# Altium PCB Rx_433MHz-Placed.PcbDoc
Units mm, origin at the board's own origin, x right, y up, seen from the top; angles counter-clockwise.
Board outline 100 x 50 mm, 4 copper layers (SIGNAL_1, SIGNAL_2, SIGNAL_3, SIGNAL_4), stack 1.58 mm thick; 51 components, 60 nets, 198 pads, 0 vias.
Unrouted connection lines stored in the file: 118.
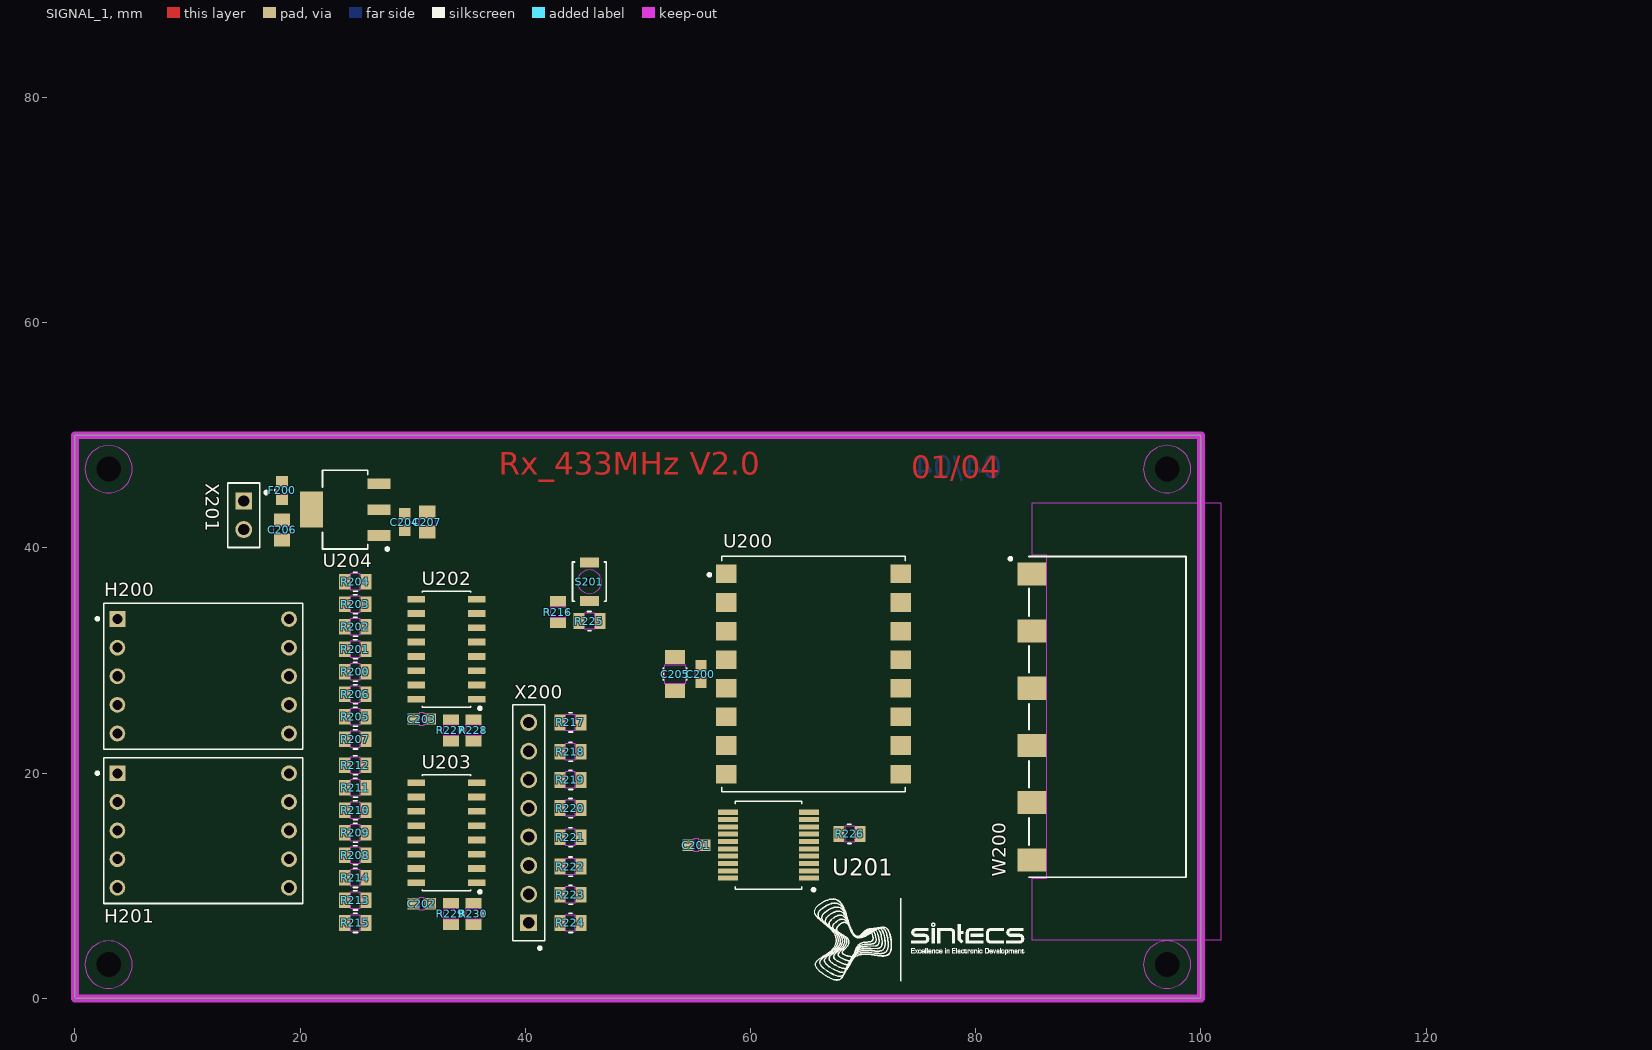
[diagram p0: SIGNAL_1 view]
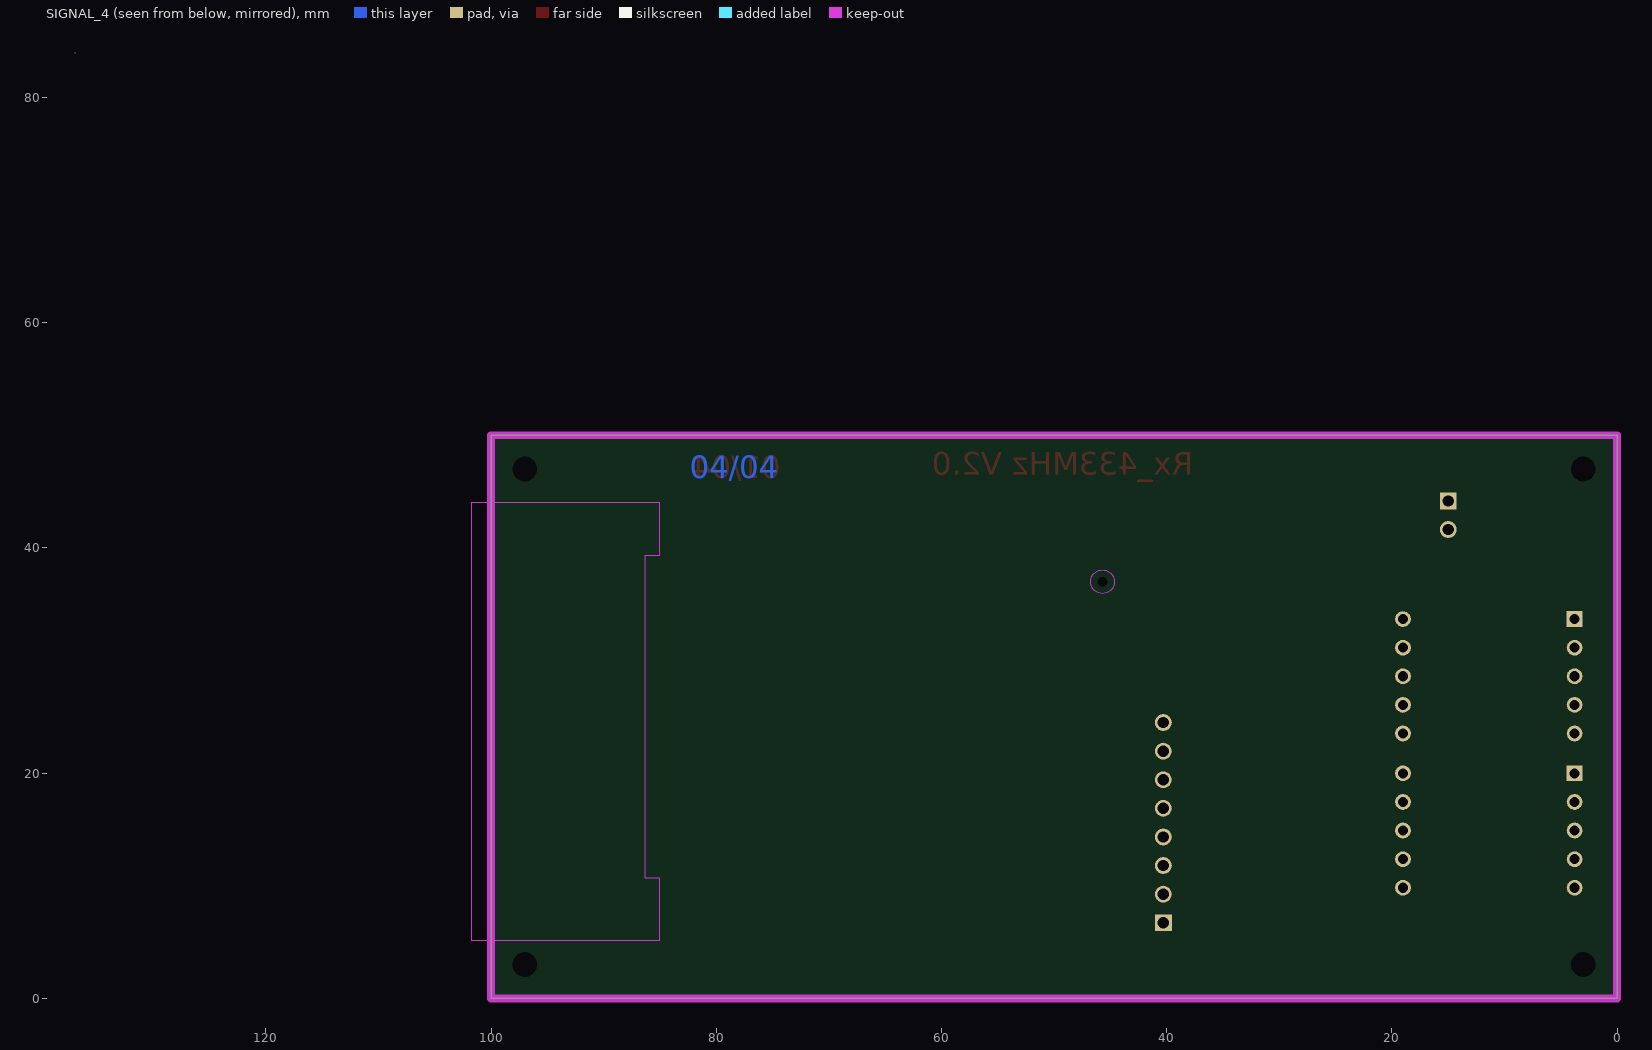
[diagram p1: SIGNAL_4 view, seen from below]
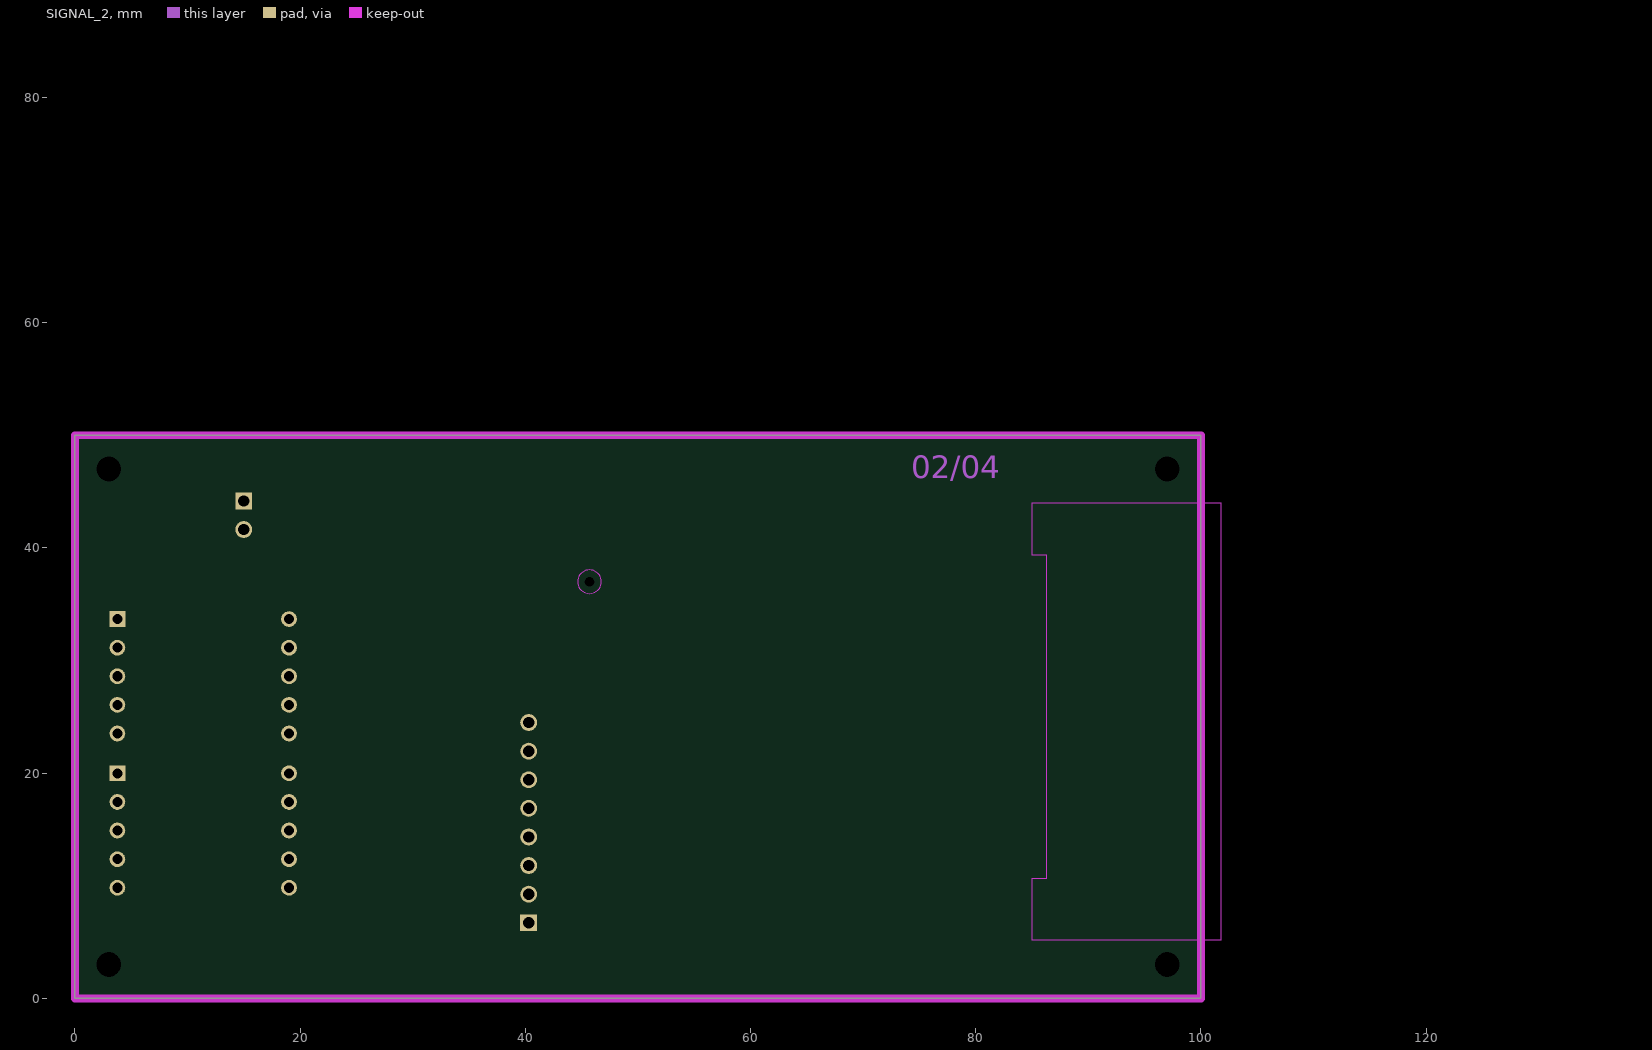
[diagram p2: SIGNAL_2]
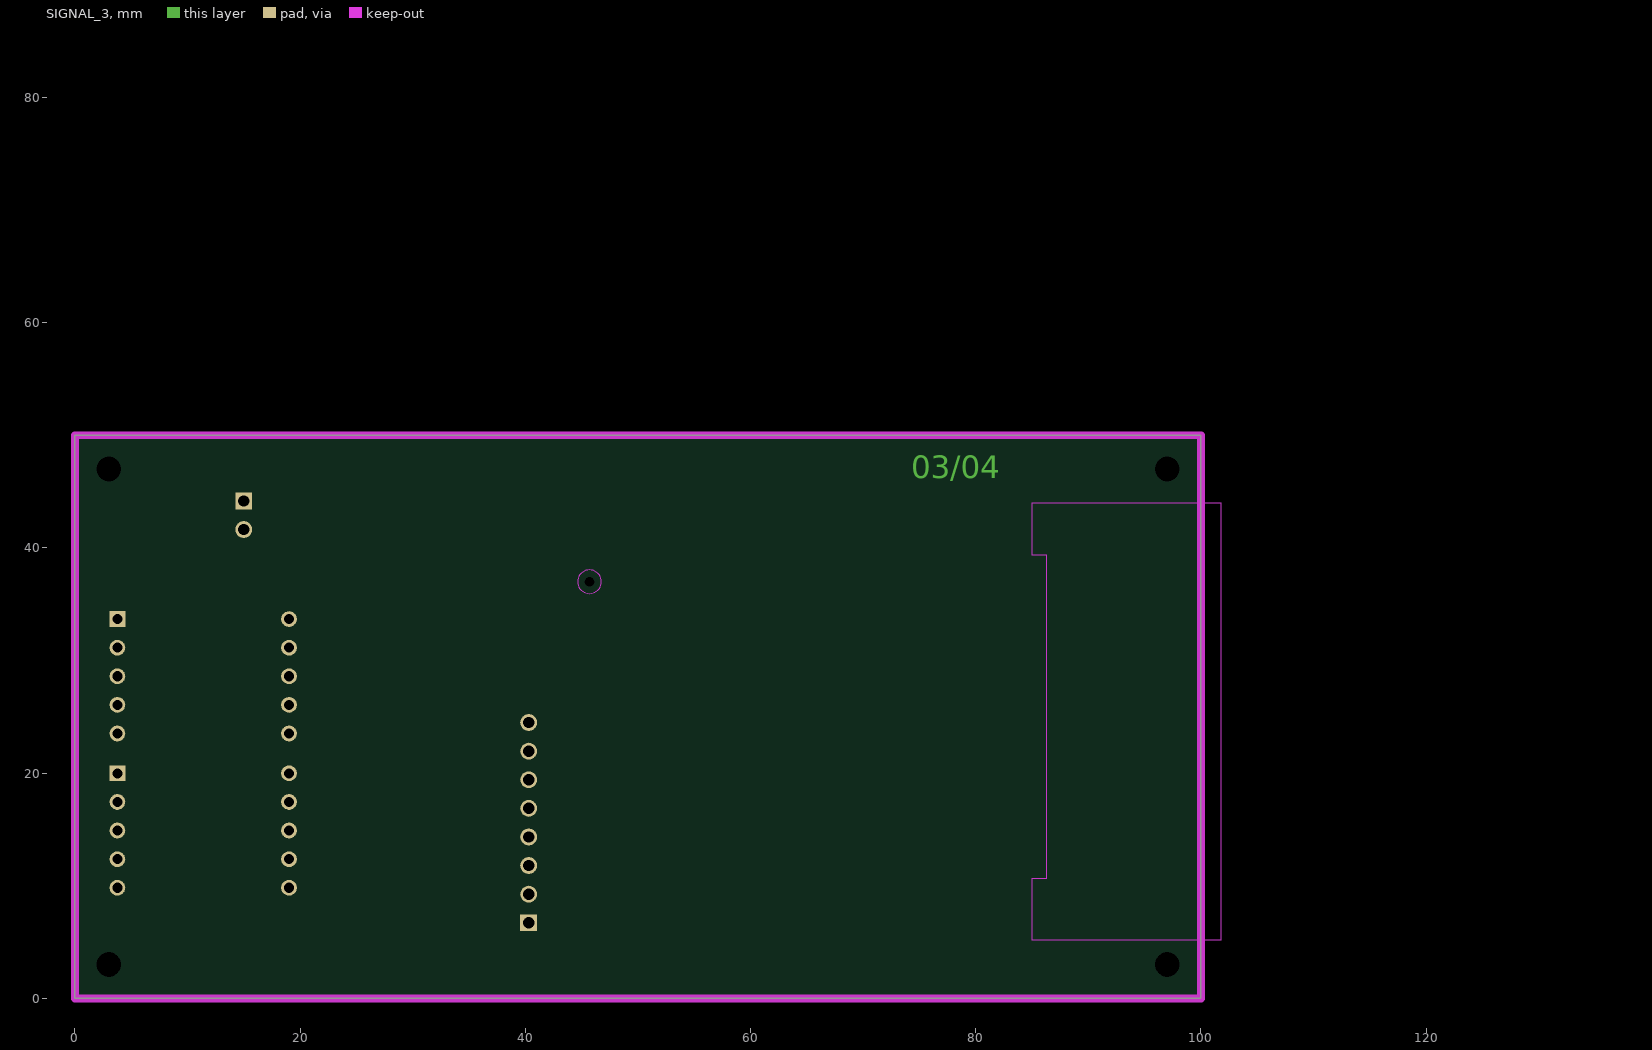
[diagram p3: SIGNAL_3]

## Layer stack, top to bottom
DIELECTRIC_1: solder mask 0.01, Dk 1
SIGNAL_1: signal copper 0.035
DIELECTRIC_3: prepreg 0.12, Dk 4.7
SIGNAL_2: signal copper 0.035
DIELECTRIC_5: prepreg 1.2, Dk 4.7
SIGNAL_3: signal copper 0.035
DIELECTRIC_7: prepreg 0.12, Dk 4.7
SIGNAL_4: signal copper 0.035
DIELECTRIC_9: solder mask 0.01, Dk 1

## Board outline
0,0 0,50 100,50 100,0

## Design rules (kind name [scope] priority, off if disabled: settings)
Clearance Clearance_50R [InNetClass('50R')] p1: gap=0.6 ignorepadtopadclearanceinfootprint=FALSE except(0.2: SMDPad-SMDPad)
Clearance [All] p2: gap=0.15 ignorepadtopadclearanceinfootprint=FALSE
ComponentClearance [All] p1: gap=0.1 collisioncheckmode=3 verticalgap=0.254 showdistances=FALSE
DiffPairsRouting [All] p1: maxlimit=0.254 minlimit=0.254 mostfreqgap=0.254 toplayer_minwidth=0.15 toplayer_maxwidth=0.3 toplayer_prefwidth=0.15 midlayer1_minwidth=0.15 midlayer1_maxwidth=0.3 midlayer1_prefwidth=0.15 midlayer2_minwidth=0.15 midlayer2_maxwidth=0.3 midlayer2_prefwidth=0.15 bottomlayer_minwidth=0.15 bottomlayer_maxwidth=0.3 bottomlayer_prefwidth=0.15 maxuncoupledlength=12.7
MinimumSolderMaskSliver [All] p1: minsoldermaskwidth=0.1
PolygonConnect [All] p1: thpad.connectstyle=Relief thpad.reliefconductorwidth=0.15 thpad.reliefentries=4 thpad.polygonreliefangle="90 Angle" thpad.airgapwidth=0.15 smdpad.connectstyle=Relief smdpad.reliefconductorwidth=0.15 smdpad.reliefentries=4 smdpad.polygonreliefangle="90 Angle" smdpad.airgapwidth=0.15 via.connectstyle=Direct via.reliefconductorwidth=0.127 via.reliefentries=2 via.polygonreliefangle="90 Angle" via.airgapwidth=0.152
RoutingVias [All] p1: holewidth=0.3 width=0.7 viastyle="Through Hole" minholewidth=0.3 minwidth=0.7 maxholewidth=0.3 maxwidth=0.7
SilkToSilkClearance [All] p1: silktosilkclearance=0.1
SolderMaskExpansion SolderMaskExpansion_Via [IsVia] p1: expansion=0.075 istentingtop=FALSE soldermaskfromhole=TRUE
SolderMaskExpansion [All] p2: expansion=0.1 istentingtop=FALSE
SupplyNets "Schematic Supply Nets_1" [InNet('3V3_RX')] p1: voltage=0.000
SupplyNets "Schematic Supply Nets" [InNet('GND_RX')] p2: voltage=0.000
UnRoutedNet [All] p1: checkbadconnections=TRUE
Width "Width for 50E_SE" [InNetClass('50R')] p1: maxlimit=0.2 minlimit=0.185 preferedwidth=0.2 toplayer_minwidth=0.2 bottomlayer_minwidth=0.2 impedanceprofiledriven=TRUE impedanceprofileid={877E34D1-77DC-4DEE-A0FB-207FE4FBDA97} impedanceprofilevalue=50.000000 minimp=50.000000 maximp=50.000000 favimp=50.000000
Width [All] p2: maxlimit=1 minlimit=0.15 preferedwidth=0.2
25 further rules are at their usual default settings.

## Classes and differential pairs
net class 50R: RF_RX
polygon class "\"(Inherited)\"": GND_RX_L02_P002

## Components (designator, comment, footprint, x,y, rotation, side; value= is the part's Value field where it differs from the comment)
C200 "C_0603_1608X90_GENERIC" CAPC1608X90N_0603_GENERIC 55.6,28.8 r90 top value=100nF
C201 "C_0603_1608X90_GENERIC" CAPC1608X90N_0603_GENERIC 55.2,13.6 r180 top value=100nF
C202 "C_0603_1608X90_GENERIC" CAPC1608X90N_0603_GENERIC 30.8,8.4 r0 top value=100nF
C203 "C_0603_1608X90_GENERIC" CAPC1608X90N_0603_GENERIC 30.8,24.8 r0 top value=100nF
C204 "C_0603_1608X90_GENERIC" CAPC1608X90N_0603_GENERIC 29.3,42.3 r270 top value=100nF
C205 "C_1206_3216X190_GENERIC" CAPC3216X190N_1206_GENERIC 53.3,28.8 r90 top value=10uF
C206 "08051C104KAZ2A" CAPC2013X140N_AVX 18.398,41.6 r270 top value=10uF
C207 "08051C104KAZ2A" CAPC2013X140N_AVX 31.3,42.3 r270 top value=10uF
F200 "0467XXXX" RESC1608X60N_0603_GENERIC 18.4,45.1 r90 top value=500mA
H200 "HDSP-5XXX" BROADCOM_HDSP-5XXX 11.4,28.6 r0 top
H201 "HDSP-5XXX" BROADCOM_HDSP-5XXX 11.4,14.9 r0 top
R200 "R_0805_2012X60_GENERIC" RESC2012X60N_0805_GENERIC 24.9,29.001 r180 top value=120R
R201 "R_0805_2012X60_GENERIC" RESC2012X60N_0805_GENERIC 24.9,31.001 r180 top value=120R
R202 "R_0805_2012X60_GENERIC" RESC2012X60N_0805_GENERIC 24.9,33.001 r180 top value=120R
R203 "R_0805_2012X60_GENERIC" RESC2012X60N_0805_GENERIC 24.9,35.001 r180 top value=120R
R204 "R_0805_2012X60_GENERIC" RESC2012X60N_0805_GENERIC 24.9,37.002 r180 top value=120R
R205 "R_0805_2012X60_GENERIC" RESC2012X60N_0805_GENERIC 24.9,25 r180 top value=120R
R206 "R_0805_2012X60_GENERIC" RESC2012X60N_0805_GENERIC 24.9,27 r180 top value=120R
R207 "R_0805_2012X60_GENERIC" RESC2012X60N_0805_GENERIC 24.9,23 r180 top value=120R
R208 "R_0805_2012X60_GENERIC" RESC2012X60N_0805_GENERIC 24.9,12.7 r180 top value=120R
R209 "R_0805_2012X60_GENERIC" RESC2012X60N_0805_GENERIC 24.9,14.7 r180 top value=120R
R210 "R_0805_2012X60_GENERIC" RESC2012X60N_0805_GENERIC 24.9,16.701 r180 top value=120R
R211 "R_0805_2012X60_GENERIC" RESC2012X60N_0805_GENERIC 24.9,18.701 r180 top value=120R
R212 "R_0805_2012X60_GENERIC" RESC2012X60N_0805_GENERIC 24.9,20.701 r180 top value=120R
R213 "R_0805_2012X60_GENERIC" RESC2012X60N_0805_GENERIC 24.9,8.7 r180 top value=120R
R214 "R_0805_2012X60_GENERIC" RESC2012X60N_0805_GENERIC 24.9,10.7 r180 top value=120R
R215 "R_0805_2012X60_GENERIC" RESC2012X60N_0805_GENERIC 24.9,6.7 r180 top value=120R
R216 "R_0805_2012X60_GENERIC" RESC2012X60N_0805_GENERIC 42.9,34.3 r270 top value=100K
R217 "R_0805_2012X60_GENERIC" RESC2012X60N_0805_GENERIC 44,24.5 r180 top value=1K
R218 "R_0805_2012X60_GENERIC" RESC2012X60N_0805_GENERIC 44,21.9 r180 top value=1K
R219 "R_0805_2012X60_GENERIC" RESC2012X60N_0805_GENERIC 44,19.4 r180 top value=1K
R220 "R_0805_2012X60_GENERIC" RESC2012X60N_0805_GENERIC 44,16.9 r180 top value=1K
R221 "R_0805_2012X60_GENERIC" RESC2012X60N_0805_GENERIC 44,14.3 r180 top value=1K
R222 "R_0805_2012X60_GENERIC" RESC2012X60N_0805_GENERIC 44,11.7 r180 top value=1K
R223 "R_0805_2012X60_GENERIC" RESC2012X60N_0805_GENERIC 44,9.2 r180 top value=1K
R224 "R_0805_2012X60_GENERIC" RESC2012X60N_0805_GENERIC 44,6.7 r180 top value=1K
R225 "R_0805_2012X60_GENERIC" RESC2012X60N_0805_GENERIC 45.7,33.5 r0 top value=1K
R226 "R_0805_2012X60_GENERIC" RESC2012X60N_0805_GENERIC 68.8,14.6 r0 top value=100K
R227 "R_0805_2012X60_GENERIC" RESC2012X60N_0805_GENERIC 33.4,23.8 r270 top value=100K
R228 "R_0805_2012X60_GENERIC" RESC2012X60N_0805_GENERIC 35.4,23.8 r270 top value=100K
R229 "R_0805_2012X60_GENERIC" RESC2012X60N_0805_GENERIC 33.4,7.5 r270 top value=100K
R230 "R_0805_2012X60_GENERIC" RESC2012X60N_0805_GENERIC 35.4,7.5 r270 top value=100K
S201 "B3U_1000P_B" OMRON_B3U_1000P_B 45.7,37 r270 top
U200 "RXM-433-LR" LINX_RXM-433-LR 65.6,28.8 r0 top
U201 "LICAL-DEC-MS001" SOP65P780X200-20N 61.6,13.6 r180 top
U202 "CD74HC4511M" SOIC127P600X175-16N 33,31 r180 top
U203 "CD74HC4511M" SOIC127P600X175-16N 33,14.7 r180 top
U204 "LM1117MPX" SOT230P700X180-4N 25.498,43.4 r180 top
W200 "ANT-433-SP" LINX_ANT-433-SP 85,25 r270 top
X200 "M20_9770842" HARWIN_M20_9770842 40.3,15.6 r90 top
X201 "M20_9770242" HARWIN_M20_9770242 15,42.9 r270 top

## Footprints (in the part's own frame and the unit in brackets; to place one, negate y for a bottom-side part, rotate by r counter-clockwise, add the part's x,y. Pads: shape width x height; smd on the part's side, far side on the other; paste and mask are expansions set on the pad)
BROADCOM_HDSP-5XXX [mm]
  rrect1% 1.4x1.4 hole 0.9 paste-2539.97 mask-0.713: 1(-7.62,5.08)
  round 1.4 hole 0.9 paste-2539.97 mask-0.713: 2(-7.62,2.54) 3(-7.62,0) 4(-7.62,-2.54) 5(-7.62,-5.08) 6(7.62,-5.08) 7(7.62,-2.54) 8(7.62,0) 9(7.62,2.54) 10(7.62,5.08)
  silkscreen extent -9.53,-6.47 8.83,6.48, body extent -8.92,-6.57 8.93,6.58, height 8.25
CAPC1608X90N_0603_GENERIC [mm]
  rrect1% 1x1 smd paste-2539.97 mask-0.513: 1(-0.75,0) 2(0.75,0)
  SIGNAL_1 keep-out region: -0.22,-0.55 0.22,-0.55 0.22,0.55 -0.22,0.55
  body extent -1.5,-0.75 1.5,0.75, height 0.9
CAPC2013X140N_AVX [mm]
  rrect1% 1.15x1.45 smd paste-2539.97 mask-0.738: 1(-0.9,0) 2(0.9,0)
  SIGNAL_1 keep-out region: -0.28,-0.78 0.28,-0.78 0.28,0.78 -0.28,0.78
  body extent -1.73,-1.05 1.73,1.05, height 1.4
CAPC3216X190N_1206_GENERIC [mm]
  rrect1% 1.25x1.8 smd paste-2539.97 mask-0.913: 1(-1.5,0) 2(1.5,0)
  SIGNAL_1 keep-out region: -0.8,-0.95 0.8,-0.95 0.8,0.95 -0.8,0.95
  silkscreen extent -0.55,-1.05 0.55,1.05, body extent -2.4,-1.15 2.4,1.15, height 1.9
HARWIN_M20_9770242 [mm]
  rrect1% 1.5x1.5 hole 1 paste-2539.97 mask-0.763: 1(-1.27,0)
  round 1.5 hole 1 paste-2539.97 mask-0.763: 2(1.27,0)
  silkscreen extent -2.87,-1.42 2.86,2.12, body extent -2.97,-1.52 2.96,1.52, height 8.38
HARWIN_M20_9770842 [mm]
  rrect1% 1.5x1.5 hole 1 paste-2539.97 mask-0.763: 1(-8.89,0)
  round 1.5 hole 1 paste-2539.97 mask-0.763: 2(-6.35,0) 3(-3.81,0) 4(-1.27,0) 5(1.27,0) 6(3.81,0) 7(6.35,0) 8(8.89,0)
  silkscreen extent -11.26,-1.42 10.48,1.42, body extent -10.59,-1.52 10.59,1.52, height 8.34
LINX_ANT-433-SP [mm]
  rrect1% 2.05x2.55 smd paste-2539.97 mask-1.288: 1(-12.7,0) 2(-7.62,0) 3(-2.54,0) 4(2.54,0) 5(7.62,0) 6(12.7,0)
  SIGNAL_1 keep-out region: 14.35,0 14.35,1.3 -14.35,1.3 -14.35,0 -19.03,0 -19.03,16.78 19.83,16.78 19.83,0
  SIGNAL_2 keep-out region: 14.35,0 14.35,1.3 -14.35,1.3 -14.35,0 -19.03,0 -19.03,16.78 19.83,16.78 19.83,0
  SIGNAL_3 keep-out region: 14.35,0 14.35,1.3 -14.35,1.3 -14.35,0 -19.03,0 -19.03,16.78 19.83,16.78 19.83,0
  SIGNAL_4 keep-out region: 14.35,0 14.35,1.3 -14.35,1.3 -14.35,0 -19.03,0 -19.03,16.78 19.83,16.78 19.83,0
  silkscreen extent -14.24,-2.04 14.24,13.67, body extent -14.34,-1.55 14.34,13.77, height 1.5
LINX_RXM-433-LR [mm]
  rrect1% 1.8x1.65 smd paste-2539.97 mask-0.913: 1(-7.747,8.89) 2(-7.747,6.35) 3(-7.747,3.81) 4(-7.747,1.27) 5(-7.747,-1.27) 6(-7.747,-3.81) 7(-7.747,-6.35) 8(-7.747,-8.89) 9(7.747,-8.89) 10(7.747,-6.35) 11(7.747,-3.81) 12(7.747,-1.27) 13(7.747,1.27) 14(7.747,3.81) 15(7.747,6.35) 16(7.747,8.89)
  silkscreen extent -9.38,-10.45 8.15,10.45, body extent -8.9,-10.65 8.9,10.65, height 3.12
OMRON_B3U_1000P_B [mm]
  rrect1% 0.9x1.7 smd paste-2539.97 mask-0.863: 1(-1.7,0) 2(1.7,0)
  round 0 hole 0.85 unplated paste-2539.97 mask+0.925: ""(0,0)
  SIGNAL_1 keep-out region: 1.05,0 0.97,0.402 0.742,0.742 0.402,0.97 0,1.05 0,1.05 -0.402,0.97 -0.742,0.742 -0.97,0.402 -1.05,0 -1.05,0 -0.97,-0.402 -0.742,-0.742 -0.402,-0.97 0,-1.05 0,-1.05 0.402,-0.97 0.742,-0.742 0.97,-0.402 1.05,0
  SIGNAL_2 keep-out region: 1.05,0 0.97,0.402 0.742,0.742 0.402,0.97 0,1.05 0,1.05 -0.402,0.97 -0.742,0.742 -0.97,0.402 -1.05,0 -1.05,0 -0.97,-0.402 -0.742,-0.742 -0.402,-0.97 0,-1.05 0,-1.05 0.402,-0.97 0.742,-0.742 0.97,-0.402 1.05,0
  SIGNAL_3 keep-out region: 1.05,0 0.97,0.402 0.742,0.742 0.402,0.97 0,1.05 0,1.05 -0.402,0.97 -0.742,0.742 -0.97,0.402 -1.05,0 -1.05,0 -0.97,-0.402 -0.742,-0.742 -0.402,-0.97 0,-1.05 0,-1.05 0.402,-0.97 0.742,-0.742 0.97,-0.402 1.05,0
  SIGNAL_4 keep-out region: 1.05,0 0.97,0.402 0.742,0.742 0.402,0.97 0,1.05 0,1.05 -0.402,0.97 -0.742,0.742 -0.97,0.402 -1.05,0 -1.05,0 -0.97,-0.402 -0.742,-0.742 -0.402,-0.97 0,-1.05 0,-1.05 0.402,-0.97 0.742,-0.742 0.97,-0.402 1.05,0
  silkscreen extent -1.75,-1.5 1.75,1.5, body extent -2.4,-1.6 2.4,1.6, height 1.75
RESC1608X60N_0603_GENERIC [mm]
  rrect1% 0.95x1.05 smd paste-2539.97 mask-0.538: 1(-0.8,0) 2(0.8,0)
  SIGNAL_1 keep-out region: -0.3,-0.55 0.3,-0.55 0.3,0.55 -0.3,0.55
  silkscreen extent -0.08,-0.65 0.08,0.65, body extent -1.55,-0.8 1.55,0.8, height 0.6
RESC2012X60N_0805_GENERIC [mm]
  rrect1% 0.95x1.4 smd paste-2539.97 mask-0.713: 1(-0.95,0) 2(0.95,0)
  SIGNAL_1 keep-out region: -0.45,-0.7 0.45,-0.7 0.45,0.7 -0.45,0.7
  silkscreen extent -0.2,-0.85 0.15,0.85, body extent -1.7,-0.95 1.7,0.95, height 0.6
SOIC127P600X175-16N [mm]
  rrect1% 1.55x0.6 smd paste-2539.97 mask-0.788: 1(-2.7,4.445) 2(-2.7,3.175) 3(-2.7,1.905) 4(-2.7,0.635) 5(-2.7,-0.635) 6(-2.7,-1.905) 7(-2.7,-3.175) 8(-2.7,-4.445) 9(2.7,-4.445) 10(2.7,-3.175) 11(2.7,-1.905) 12(2.7,-0.635) 13(2.7,0.635) 14(2.7,1.905) 15(2.7,3.175) 16(2.7,4.445)
  silkscreen extent -3.1,-5.16 2.15,5.38, body extent -3.73,-5.25 3.73,5.25, height 1.75
SOP65P780X200-20N [mm]
  rrect1% 1.75x0.45 smd paste-2539.97 mask-0.888: 1(-3.6,2.925) 2(-3.6,2.275) 3(-3.6,1.625) 4(-3.6,0.975) 5(-3.6,0.325) 6(-3.6,-0.325) 7(-3.6,-0.975) 8(-3.6,-1.625) 9(-3.6,-2.275) 10(-3.6,-2.925) 11(3.6,-2.925) 12(3.6,-2.275) 13(3.6,-1.625) 14(3.6,-0.975) 15(3.6,-0.325) 16(3.6,0.325) 17(3.6,0.975) 18(3.6,1.625) 19(3.6,2.275) 20(3.6,2.925)
  silkscreen extent -4.12,-3.9 2.95,4.08, body extent -4.75,-4 4.75,4, height 2
SOT230P700X180-4N [mm]
  rrect1% 2.05x0.95 smd paste-2539.97 mask-1.038: 1(-1.5,2.3) 2(-1.5,0) 3(-1.5,-2.3)
  rrect1% 2.05x3.2 smd paste-2539.97 mask-1.613: 4(4.5,0)
  silkscreen extent -2.37,-3.5 3.5,3.62, body extent -2.8,-3.6 5.8,3.6, height 1.8

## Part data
C200 C201 C202 C203 C204: "100nF 25V 10%", Capacitance=100000, Dielectric=X7R, Manufacturer=MURATA, MPN=GRM188R71E104KA01D, Package=0603, Part Name="Ceramic chip capacitor 0603-1608x90, generic", Tolerance=10, Voltage=25V
C205: "10uF 25V 10%", Capacitance=10000000, Dielectric=X7R, Manufacturer=AVX, Max Temp=+125, Min Temp=-55, MPN=12063C106KAT2A, Package=1206, Part Name="Cheramic chip capacitor 1206-3216x190, generic", Tolerance=10, Voltage=25V
C206 C207: "10uF 25V 10%", Capacitance=10000000, Dielectric=X5R, Manufacturer=AVX, MPN=08053D106KAT2A, Package=0805, Part Name="0805 chip 100nF 10% 100V X7R", Tolerance=10, Voltage=25V
F200: "Thin film 0603 fuse very fast acting", Current=0.5, Manufacturer=LITTELFUSE, Max Temp=+90, Min Temp=-55, MPN=0467.500NRHF, Package=0603, Part Name="Thin film 0603 very fast acting", Voltage=32V
H200 H201: "7 Segment Display Module Red, 1,85V, 20mA. THT", Color=Red, Manufacturer=BROADCOM, Max Temp=85, Min Temp=-25, MPN=HDSP-515A, Part Name="Single Digit LED Numeric Display, Blue color"
R200 R201 R202 R203 R204 R205 R206 R207 R208 R209 R210 R211 R212 R213 R214 R215: "0.125W 5% 120R 50V", Manufacturer=YAGEO, MPN=RC0805JR-07120RL, Package=0805, Part Name="resistor_0805-2012x60 generic", Tolerance=5%
R216 R226 R227 R228 R229 R230: "0.125W 5% 100K 50V", Manufacturer=YAGEO, MPN=RC0805JR-07100KL, Package=0805, Part Name="resistor_0805-2012x60 generic", Tolerance=5%
R217 R218 R219 R220 R221 R222 R223 R224 R225: "Resistor_1K_1%_0805", Manufacturer=MULTICOMP, MPN=MCPWR05FTEW1001, Package=0805, Part Name="resistor_0805-2012x60 generic", Tolerance=1%
S201: "Ultra-small Tactile Switch", Manufacturer=OMRON, Max Temp=0, MPN=B3U-1000P-B
U200: "LR Series Receiver, Low Voltage, Low Power", Manufacturer="Linx Technologies", Max Temp=70, Min Temp=-40, Package=custom
U201: "MS Series Remote Controler Decoder, Low Voltage, Low Power", Manufacturer="LINX TECHNOLOGIES", Max Temp=85, Min Temp=-40, MPN=LICAL-DEC-MS001-T, Package=SOP-20
U202 U203: "Leddriver BCD to 7 segment 1 Digit", Manufacturer="TEXAS INSTRUMENTS", Max Temp=125, Min Temp=-55, Package=SOIC-16N
U204: "3.3V/1A fixed regulator", Manufacturer=ON-SEMI, MPN=NCP1117LPST33T3G, Package=SOT, Part Name="800mA Low-Dropout Linear Regulator, SOT223"
W200: "433MHz 50 Ohm Antenna module", Manufacturer="Linx Technologies", Max Temp=130, Min Temp=-40, Package=custom
X200: "1x8 pin 2.54 mm pitch vertical header", Manufacturer=HARWIN, MPN=M20-9770842, Package=header, Part Name=STD_HEADER_1x8_2.54_THT
X201: "1x2 pin 2.54 mm pitch vertical header", Manufacturer=HARWIN, MPN=M20-9770242, Package=header, Part Name=STD_HEADER_1x2_2.54_THT

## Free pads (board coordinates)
  round 0 hole 2.2 unplated paste-2539.97 mask+1.6: ""(3,3) ""(3,47) ""(97,3) ""(97,47)
  round 0.025 smd far side paste-2539.97 mask-127: ""(7,6.05) ""(80.8,5.2) ""(136.95,83.95)

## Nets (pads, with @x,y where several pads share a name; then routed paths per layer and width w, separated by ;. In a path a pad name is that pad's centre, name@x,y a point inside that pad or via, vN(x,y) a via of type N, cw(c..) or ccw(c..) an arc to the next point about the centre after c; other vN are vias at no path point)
3V3_RX: C200.1 C201.1 C202.1 C203.1 C204.1 C205.1 C207.1 R215.1 R226.2 R227.2 R228.2 R229.2 R230.2 S201.1 U200.5 U201.15 U201.16 U202.16 U203.16 U204.2 U204.4
DEC_MODE_IND: R207.1 U201.10
GND_RX: C200.2 C201.2 C202.2 C203.2 C204.2 C205.2 C206.2 C207.2 H200.3 H200.8 H201.3 H201.8 R216.1 U200.4 U200.15 U201.3 U201.4 U201.5 U201.6 U201.8 U202.5 U202.8 U203.5 U203.8 U204.1 W200.2 W200.3 W200.4 W200.5 W200.6 X201.2
NetC206_1: C206.1 F200.1 X201.1
NetF200_2: F200.2 U204.3
NetH200_1: H200.1 R204.2
NetH200_2: H200.2 R203.2
NetH200_4: H200.4 R202.2
NetH200_5: H200.5 R207.2
NetH200_6: H200.6 R201.2
NetH200_7: H200.7 R200.2
NetH200_9: H200.9 R205.2
NetH200_10: H200.10 R206.2
NetH201_1: H201.1 R212.2
NetH201_2: H201.2 R211.2
NetH201_4: H201.4 R210.2
NetH201_5: H201.5 R215.2
NetH201_6: H201.6 R209.2
NetH201_7: H201.7 R208.2
NetH201_9: H201.9 R213.2
NetH201_10: H201.10 R214.2
NetR200_1: R200.1 U202.13
NetR201_1: R201.1 U202.12
NetR202_1: R202.1 U202.11
NetR203_1: R203.1 U202.10
NetR204_1: R204.1 U202.9
NetR205_1: R205.1 U202.15
NetR206_1: R206.1 U202.14
NetR208_1: R208.1 U203.13
NetR209_1: R209.1 U203.12
NetR210_1: R210.1 U203.11
NetR211_1: R211.1 U203.10
NetR212_1: R212.1 U203.9
NetR213_1: R213.1 U203.15
NetR214_1: R214.1 U203.14
NetR216_2: R216.2 R225.1 S201.2
NetR217_1: R217.1 U201.1
NetR217_2: R217.2 U202.7 X200.8
NetR218_1: R218.1 U201.2
NetR218_2: R218.2 U202.1 X200.7
NetR219_1: R219.1 U201.13
NetR219_2: R219.2 U202.2 X200.6
NetR220_1: R220.1 U201.14
NetR220_2: R220.2 U202.6 X200.5
NetR221_1: R221.1 U201.17
NetR221_2: R221.2 U203.7 X200.4
NetR222_1: R222.1 U201.18
NetR222_2: R222.2 U203.1 X200.3
NetR223_1: R223.1 U201.19
NetR223_2: R223.2 U203.2 X200.2
NetR224_1: R224.1 U201.20
NetR224_2: R224.2 U203.6 X200.1
NetR225_2: R225.2 U201.11
NetR226_1: R226.1 U201.7
NetR227_1: R227.1 U202.4
NetR228_1: R228.1 U202.3
NetR229_1: R229.1 U203.4
NetR230_1: R230.1 U203.3
RF_RX: U200.16 W200.1
RX_DATA: U200.8 U201.12
pads on no net: S201. U200.1 U200.2 U200.3 U200.6 U200.7 U200.9 U200.10 U200.11 U200.12 U200.13 U200.14 U201.9

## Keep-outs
SIGNAL_1:
  region: 99.1,3 ccw(c97,3) 97,5.1 ccw(c97,3) 94.9,3 ccw(c97,3) 97,0.9 ccw(c97,3)
  region: 5.1,3 ccw(c3,3) 3,5.1 ccw(c3,3) 0.9,3 ccw(c3,3) 3,0.9 ccw(c3,3)
  region: 5.1,47 ccw(c3,47) 3,49.1 ccw(c3,47) 0.9,47 ccw(c3,47) 3,44.9 ccw(c3,47)
  region: 99.1,47 ccw(c97,47) 97,49.1 ccw(c97,47) 94.9,47 ccw(c97,47) 97,44.9 ccw(c97,47)
Keep-Out Layer:
  the board outline again, w0.7

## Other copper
SIGNAL_1:
  pour cut-out: 99.1,3 ccw(c97,3) 97,5.1 ccw(c97,3) 94.9,3 ccw(c97,3) 97,0.9 ccw(c97,3)
  pour cut-out: 5.1,3 ccw(c3,3) 3,5.1 ccw(c3,3) 0.9,3 ccw(c3,3) 3,0.9 ccw(c3,3)
  pour cut-out: 5.1,47 ccw(c3,47) 3,49.1 ccw(c3,47) 0.9,47 ccw(c3,47) 3,44.9 ccw(c3,47)
  pour cut-out: 99.1,47 ccw(c97,47) 97,49.1 ccw(c97,47) 94.9,47 ccw(c97,47) 97,44.9 ccw(c97,47)
  text "Rx_433MHz V2.0" at 37.656,46.5 h2
  text "01/04" at 74.286,46.175 h2
  text "Layer 01/04 Top" at 33.324,-23.065 h2
SIGNAL_2:
  text "02/04" at 74.256,46.175 h2
  text "Layer 02/04" at 33.324,-23.065 h2
SIGNAL_3:
  text "03/04" at 74.256,46.175 h2
  text "Layer 03/04" at 33.324,-23.065 h2
SIGNAL_4:
  text "04/04" at 82.364,46.175 h2
  text "Layer 04/04 Bottom" at 69.073,-23.065 h2

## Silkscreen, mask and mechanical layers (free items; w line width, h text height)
Top Overlay:
  drawing of 94 lines, arcs and shapes, not listed
  text "SILKSCREEN TOP" at 66.497,-23.235 h2
DIELECTRIC_1:
  text "SOLDERMASK TOP" at 33.334,-23.005 h2
DIELECTRIC_9:
  text "SOLDERMASK BOTTOM" at 33.344,-23.005 h2
Top Assembly:
  text "U204" at 24.55,41.7 h1 r90
  text "X201" at 15.4,41.25 h1 r90
  text "U202" at 33.45,29.45 h1 r90
  text "U200" at 63.6,28.35 h1
  text "W200" at 90.4,24.65 h1
  text "H200" at 6.6,23.1 h1
  text "X200" at 40.75,13.85 h1 r90
  text "U203" at 33.55,13 h1 r90
  text "U201" at 60,12.95 h1
  text "H201" at 6.6,9.25 h1
  text "Assembly Drawing Top" at 33.604,-23.29 h2
Default User Layer:
  lines w0.025: 1,1 1,49 ; 1,1 85,1 ; 1,1 1,49 ; 1,1 85,1 ; 1,49 85,49 ; 1,49 85,49 ; 85,1 85,49 ; 85,1 85,49
VSCORE_DETAIL:
  lines w0.1: 0,50 100,50
  text "VSCORE DETAIL" at 33.334,-23.005 h2
Panel Dimension:
  circle w0.2: c3,47 r1.1
  circle w0.2: c97,47 r1.1
  circle w0.2: c97,3 r1.1
  circle w0.2: c3,3 r1.1
  lines w0.2: 0,0 0,50 100,50 100,0 0,0
  text "Panel Drawing" at 33.864,-23.295 h2
Single Board Dimensions:
  circle w0.2: c3,3 r1.1
  circle w0.2: c97,3 r1.1
  circle w0.2: c97,47 r1.1
  circle w0.2: c3,47 r1.1
  lines w0.2: 0,0 100,0 100,50 0,50 0,0
  text "Single Board Dimensions" at 33.334,-23.005 h2
TitleBlock_Mirrored:
  drawing of 102 lines, arcs and shapes, not listed
  text "PROJECT:" at 76.049,-13.849 h0.76
  text "TX & RX 433MHZ UT Scintilla Workshop" at 68.987,-15.551 h2
  text "DRAWN BY:" at 76.049,-17.659 h0.76
  text "Lesley Snijder/Henk Mengerink" at 69.191,-19.281 h2
  text "LAYER:" at 76.049,-21.469 h0.76
  text "DATE:" at 16.613,-25.279 h0.76
  text "REV:" at 26.519,-25.279 h0.76
  text "DWG NO:" at 76.049,-25.279 h0.76
  text "30 Apr2021" at 12.549,-27.041 h2
  text "2.0" at 23.217,-27.041 h2
  text "THE INFORMATION HEREIN IS PROPRIETARY TO YOUR DESIGN COMPANY" at 111.709,-27.628 h0.64
TittleBlock:
  drawing of 102 lines, arcs and shapes, not listed
  text "PROJECT:" at 26.889,-13.869 h0.76
  text "TX & RX 433MHZ UT Scintilla Workshop" at 33.747,-15.531 h2
  text "DRAWN BY:" at 26.889,-17.679 h0.76
  text "Lesley Snijder/Henk Mengerink" at 33.747,-19.301 h2
  text "LAYER:" at 26.889,-21.489 h0.76
  text "DWG NO:" at 26.889,-25.299 h0.76
  text "REV:" at 76.419,-25.299 h0.76
  text "DATE:" at 86.325,-25.299 h0.76
  text "2.0" at 79.721,-27.061 h2
  text "30 Apr 2021" at 90.389,-27.061 h2
  text "THE INFORMATION HEREIN IS PROPRIETARY TO YOUR DESIGN COMPANY" at -8.771,-27.648 h0.64
Drill Drawing:
  lines w0.15: -22.95,-45.95 134.55,-45.95 ; -22.95,-39.95 134.55,-39.95 ; -22.95,-62.45 -22.95,-30.95 134.55,-30.95 134.55,-62.45 -22.95,-62.45
  text "E" at 3,96 h2
  text "E" at 97,96 h2
  text "A" at 66.42,91.24 h2
  text "A" at 71.68,91.24 h2
  text "A" at 43.09,90.65 h2
  text "A" at 56.5,90.65 h2
  text "A" at 31,88.55 h2
  text "A" at 6.98,88.49 h2
  text "D" at 43.1,88 h2
  text "D" at 56.5,88 h2
  text "A" at 49.85,87.74 h2
  text "A" at 38.54,86.13 h2
  text "A" at 18.66,85.93 h2
  text "A" at 78.64,85 h2
  text "A" at 82.3,84.67 h2
  text "A" at 41.17,84.05 h2
  text "A" at 54.57,84.05 h2
  text "A" at 83.76,81.72 h2
  text "A" at 78.92,80.83 h2
  text "A" at 58.77,79.72 h2
  text "A" at 51.12,78.4 h2
  text "A" at 54.98,78.4 h2
  text "A" at 65.43,76.73 h2
  text "A" at 70.52,76.73 h2
  text "A" at 73.05,76.73 h2
  text "A" at 6.89,76.65 h2
  text "A" at 83.76,76.64 h2
  text "A" at 51.12,75.85 h2
  text "A" at 54.98,75.85 h2
  text "A" at 68.6,75.09 h2
  text "A" at 30.84,74.25 h2
  text "A" at 56.5,74.18 h2
  text "A" at 51.12,73.3 h2
  text "A" at 79.23,73.15 h2
  text "A" at 83.76,71.56 h2
  text "A" at 51.12,70.8 h2
  text "A" at 79.23,70.6 h2
  text "A" at 65.64,70.55 h2
  text "A" at 68.69,69.57 h2
  text "A" at 54.9,69.55 h2
  text "A" at 18.54,68.46 h2
  text "A" at 57.4,68.46 h2
  text "A" at 65.65,68.25 h2
  text "A" at 51.12,68.2 h2
  text "A" at 69.01,67.28 h2
  text "A" at 83.76,66.48 h2
  text "A" at 69.01,65.96 h2
  text "A" at 51.12,65.7 h2
  text "A" at 70.96,64.65 h2
  text "A" at 79.05,64.65 h2
  text "A" at 69.7,64.39 h2
  text "A" at 51.12,63.15 h2
  text "A" at 6.78,62.23 h2
  text "C" at 60.23,61.67 h2
  text "A" at 83.76,61.4 h2
  text "A" at 51.12,60.6 h2
  text "A" at 64.84,60.6 h2
  text "A" at 30.67,59.95 h2
  text "C" at 60.23,59.13 h2
  text "A" at 64.85,59.1 h2
  text "A" at 78.85,57.44 h2
  text "E" at 3,52 h2
  text "E" at 97,52 h2
  text "E" at 3,46 h2
  text "E" at 97,46 h2
  text "A" at 4.63,41.86 h2
  text "A" at 29.48,41.21 h2
  text "A" at 66.43,40.71 h2
  text "C" at 45.53,40.68 h2
  text "C" at 48.07,40.68 h2
  text "A" at 53.83,40.7 h2
  text "B" at 3.055,38.58 h2
  text "B" at 18.295,38.58 h2
  text "A" at 47.53,38 h2
  text "A" at 34.53,37.67 h2
  text "A" at 50.78,36.1 h2
  text "A" at 46.55,36.06 h2
  text "B" at 3.055,36.04 h2
  text "B" at 18.295,36.04 h2
  text "A" at 46.56,34.91 h2
  text "A" at 77.44,34.69 h2
  text "A" at 82.12,34.69 h2
  text "A" at 50.78,34.2 h2
  text "A" at 74.65,34.16 h2
  text "A" at 34.53,33.87 h2
  text "B" at 3.055,33.5 h2
  text "B" at 18.295,33.5 h2
  text "A" at 39.37,32.92 h2
  text "A" at 42.26,32.6 h2
  text "A" at 50.79,31.77 h2
  text "A" at 83.11,31.62 h2
  text "A" at 39.37,31.02 h2
  text "B" at 3.055,30.96 h2
  text "B" at 18.295,30.96 h2
  text "A" at 51.5,29.2 h2
  text "A" at 78.52,28.46 h2
  text "B" at 3.055,28.42 h2
  text "B" at 18.295,28.42 h2
  text "A" at 37.98,28.32 h2
  text "A" at 26.55,26.7 h2
  text "A" at 83.11,26.54 h2
  text "A" at 30.1,26.47 h2
  text "A" at 51.5,26.21 h2
  text "A" at 25.5,26 h2
  text "A" at 14.55,24.94 h2
  text "C" at 42,23.78 h2
  text "A" at 30.78,23.09 h2
  text "A" at 37.97,23.1 h2
  text "A" at 51.12,22.25 h2
  text "B" at 2.905,21.78 h2
  text "B" at 18.145,21.78 h2
  text "A" at 83.11,21.46 h2
  text "C" at 42,21.24 h2
  text "A" at 34.53,19.89 h2
  text "B" at 2.905,19.24 h2
  text "B" at 18.145,19.24 h2
  text "C" at 42,18.7 h2
  text "A" at 48.38,18.56 h2
  text "B" at 2.905,16.7 h2
  text "B" at 18.145,16.7 h2
  text "A" at 48.38,16.66 h2
  text "A" at 83.11,16.38 h2
  text "C" at 42,16.16 h2
  text "A" at 34.53,16.08 h2
  text "A" at 63.03,15.82 h2
  text "A" at 39.39,15.15 h2
  text "A" at 60.27,14.54 h2
  text "B" at 2.905,14.16 h2
  text "B" at 18.145,14.16 h2
  text "A" at 78.41,14.04 h2
  text "A" at 66.43,13.85 h2
  text "C" at 42,13.62 h2
  text "A" at 39.37,13.24 h2
  text "A" at 60.24,12.92 h2
  text "A" at 49.35,12.9 h2
  text "A" at 51.85,11.73 h2
  text "B" at 2.905,11.62 h2
  text "B" at 18.145,11.62 h2
  text "A" at 63.25,11.59 h2
  text "A" at 83.11,11.3 h2
  text "C" at 42,11.08 h2
  text "A" at 63.39,10.63 h2
  text "A" at 39.19,9.84 h2
  text "A" at 63.39,9.31 h2
  text "A" at 66.49,8.88 h2
  text "A" at 58.79,8.73 h2
  text "A" at 26,8.7 h2
  text "A" at 30.05,8.7 h2
  text "C" at 42,8.54 h2
  text "A" at 37.1,7.14 h2
  text "A" at 52.5,6.8 h2
  text "D" at 55.15,6.8 h2
  text "A" at 13.66,6.75 h2
  text "C" at 42,6 h2
  text "A" at 30.94,5.5 h2
  text "E" at 3,2 h2
  text "E" at 97,2 h2
  text "Through Holes" at 47.75,-34.7 h1.5
  text "All Drills (unless specified) +/- 0.1000 (MM)" at 25.675,-37.7 h1.5
  text "Symbol" at -19.208,-43.7 h1.5
  text "Diameter" at 1.834,-43.7 h1.5
  text "Tolerance" at 29.561,-43.7 h1.5
  text "Plated" at 52.798,-43.7 h1.5
  text "HoleName" at 85.805,-43.7 h1.5
  text "Quantity" at 120.337,-43.7 h1.5
  text "A" at -15.45,-48.2 h1.5
  text "0.3000" at 3.379,-48.2 h1.5
  text "+/- 0.1000" at 29.132,-48.2 h1.5
  text "Yes" at 55.01,-48.2 h1.5
  text "Rnd 0.30 +/-Tol 0.10" at 77.714,-48.2 h1.5
  text "114" at 124.046,-48.2 h1.5
  text "B" at -15.45,-51.2 h1.5
  text "0.9000" at 3.379,-51.2 h1.5
  text "+/- 0.1000" at 29.132,-51.2 h1.5
  text "Yes" at 55.01,-51.2 h1.5
  text "Rnd 0.90 +/-Tol 0.10" at 77.714,-51.2 h1.5
  text "20" at 124.766,-51.2 h1.5
  text "C" at -15.45,-54.2 h1.5
  text "1.0000" at 3.402,-54.2 h1.5
  text "+/- 0.1000" at 29.132,-54.2 h1.5
  text "Yes" at 55.01,-54.2 h1.5
  text "Rnd 1.00 +/-Tol 0.10" at 77.74,-54.2 h1.5
  text "12" at 124.78,-54.2 h1.5
  text "D" at -15.45,-57.2 h1.5
  text "0.8500" at 3.385,-57.2 h1.5
  text "+/- 0.1000" at 29.132,-57.2 h1.5
  text "No" at 55.767,-57.2 h1.5
  text "Rnd 0.85 +/-Tol 0.10 Non-Plated" at 69.797,-57.2 h1.5
  text "3" at 125.55,-57.2 h1.5
  text "E" at -15.45,-60.2 h1.5
  text "2.2000" at 3.379,-60.2 h1.5
  text "+/- 0.1000" at 29.132,-60.2 h1.5
  text "No" at 55.767,-60.2 h1.5
  text "Rnd 2.20 +/-Tol 0.10 Non-Plated" at 69.79,-60.2 h1.5
  text "8" at 125.55,-60.2 h1.5

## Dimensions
0,50 to 3,1.9 on Single Board Dimensions
0,50 to 100,50 on Single Board Dimensions
97,1.9 to 100,50 on Single Board Dimensions
0,0 to 1.9,3 on Single Board Dimensions
0,0 to 0,50 on Single Board Dimensions
0,50 to 1.9,47 on Single Board Dimensions
3,3 to 5.6,4.3 on Single Board Dimensions
0,50 to 100,50 on Panel Dimension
